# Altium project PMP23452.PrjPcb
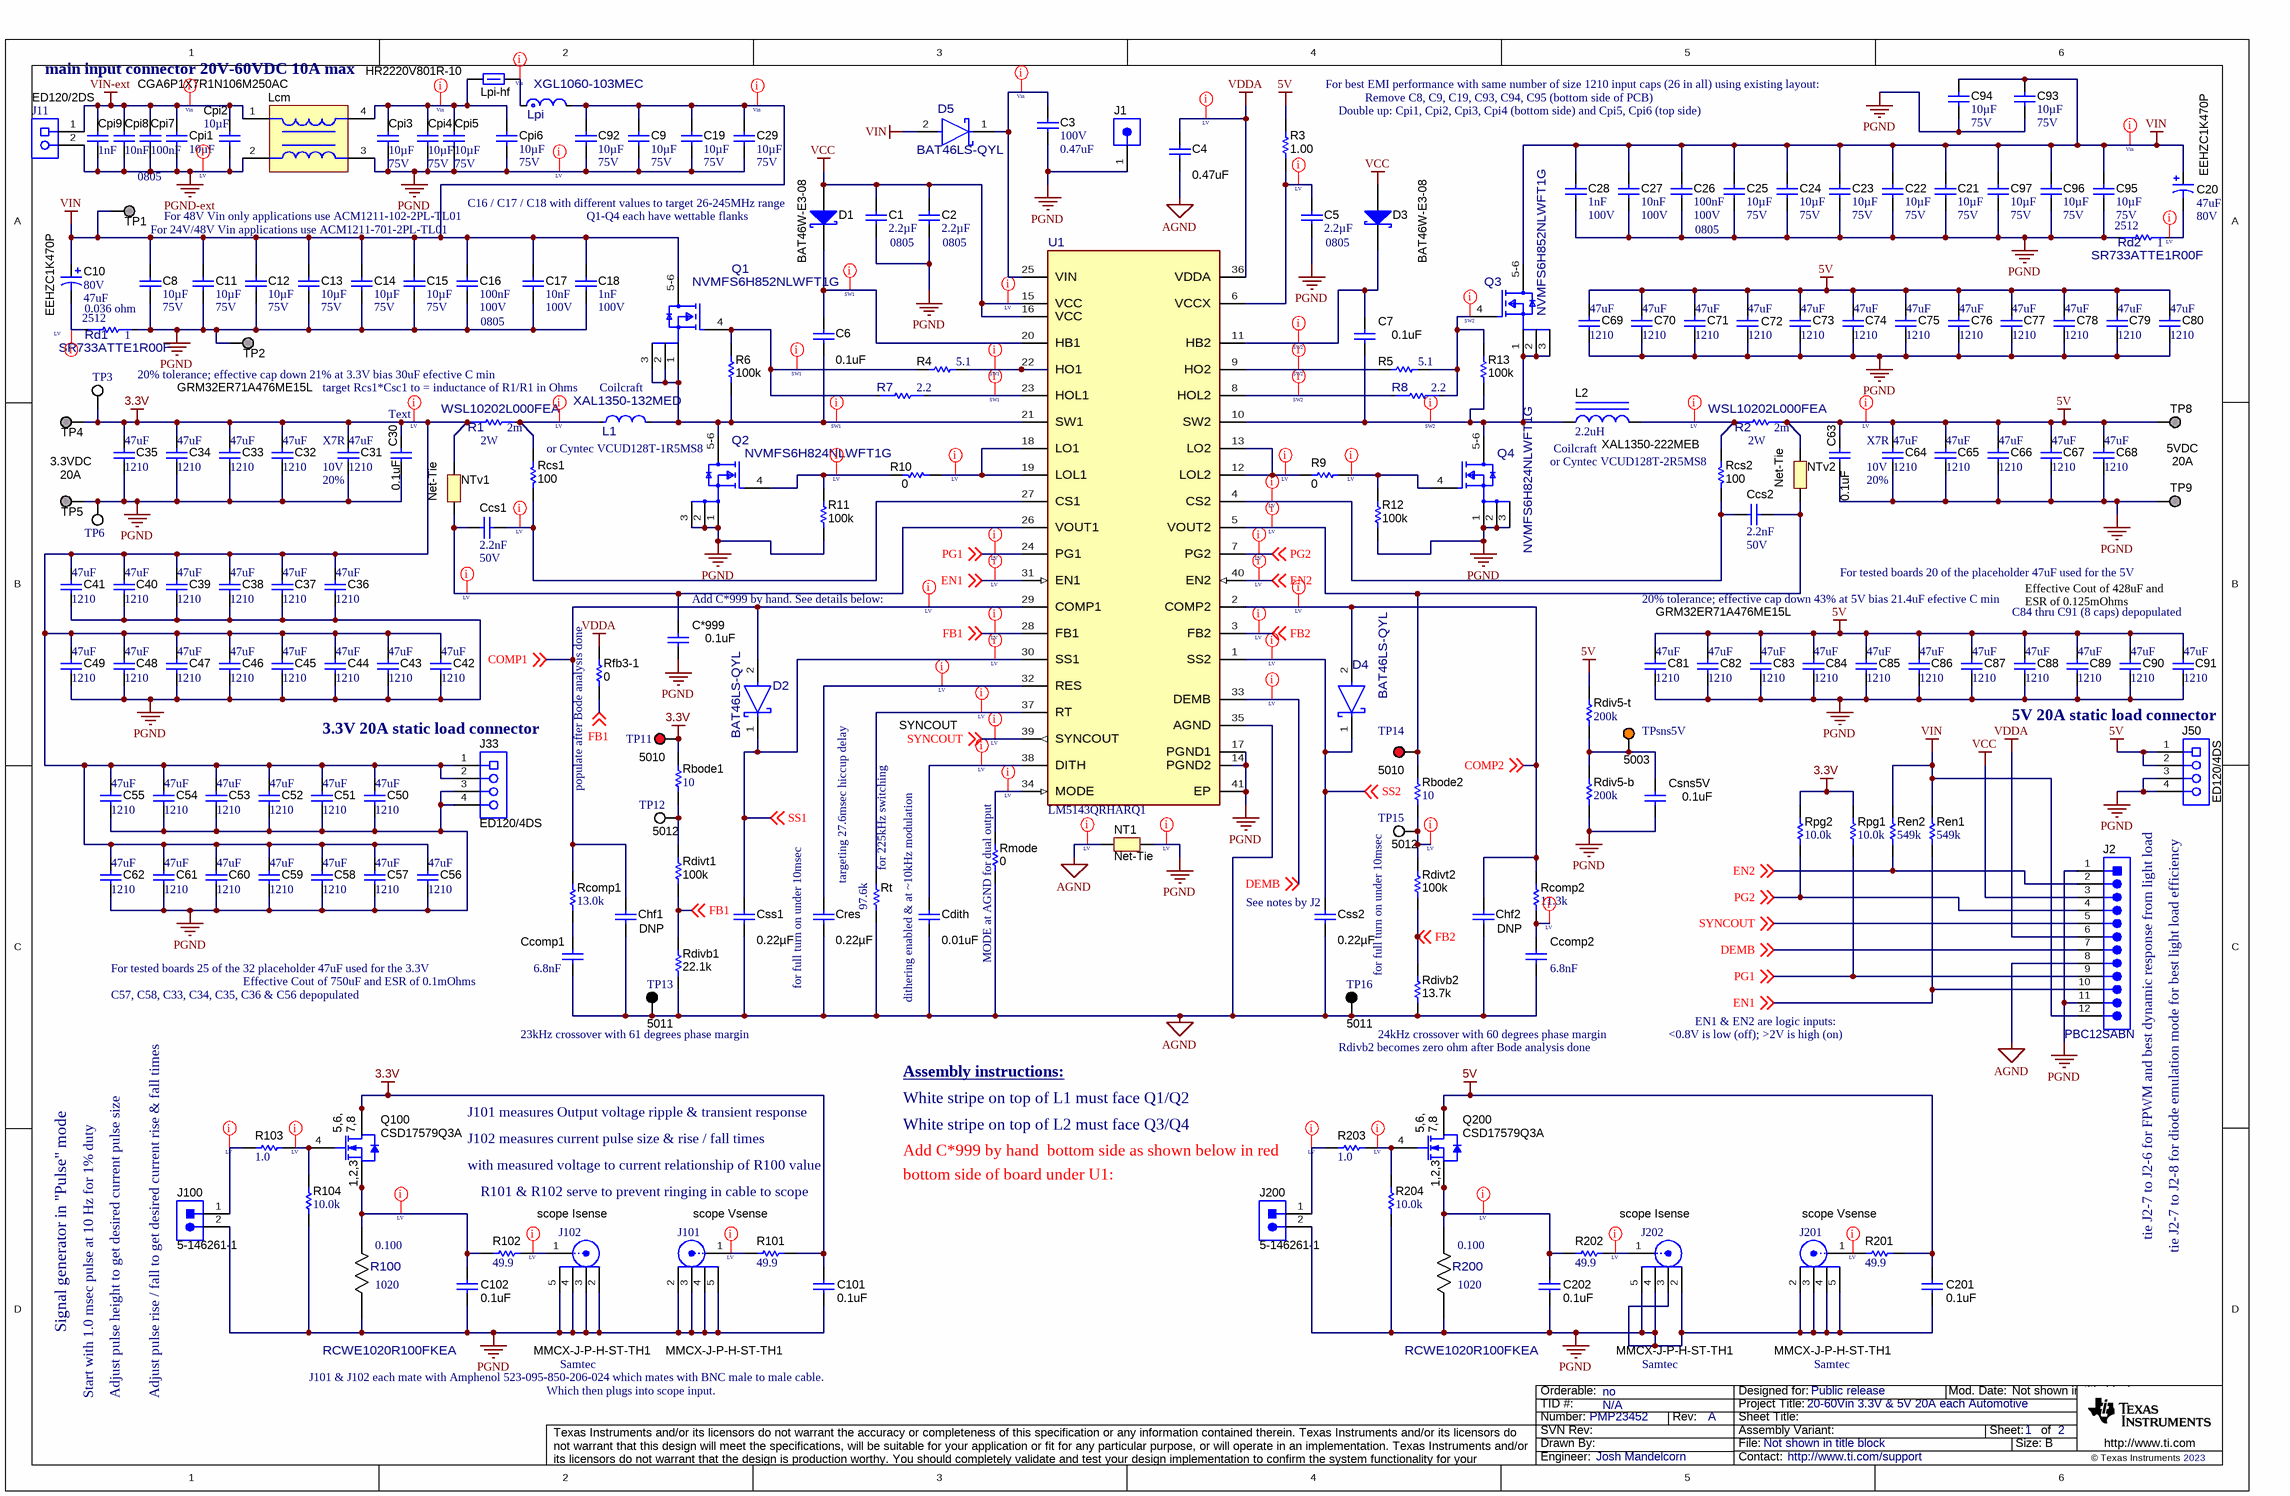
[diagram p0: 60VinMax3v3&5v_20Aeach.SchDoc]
TID: N/A; TechSupport: http://www.ti.com/support; SCH_Rev: A; PRJ_Title: 20-60Vin 3.3V & 5V 20A each Automotive; PRJ_Number: PMP23452; PRJ_Engineer: Josh Mandelcorn; PRJ_Customer: Public release; PCB_Rev: A; PCB_Layout: PMP23452; Orderable: no; EVM_Orderable: no; CopyrightYear: 2023
2 sheets, 234 parts. Net scope: global (net labels, ports and power ports of the same name join across sheets).
Board file: PMP23452.PcbDoc
Sheets:
  60VinMax3v3&5v_20Aeach.SchDoc
  PMP23452_Hardware&misc.SchDoc

## Sheet 60VinMax3v3&5v_20Aeach.SchDoc
size 431 x 279 mm; Date: Not shown in title block; ApprovedBy: Not shown in title block; CheckedBy: Not shown in title block; Author: Not shown in title block; CompanyName: Not shown in title block; Engineer: Not shown in title block; Organization: Not shown in title block; Address1: Not shown in title block; Address2: Not shown in title block; Address3: Not shown in title block; Address4: Not shown in title block; DocumentNumber: 1; Revision: Use project parameter SCH_Rev; SheetNumber: 1; SheetTotal: 2; PageSetup: Record=PageOptions¦CenterHorizontal=True¦CenterVertical=True¦PrintScale=0.96¦XCorrection=1.00¦YCorrection=1.00¦PrintKind=0¦BorderSize=5000000¦LeftOffset=0¦BottomOffset=0¦Orientation=2¦PaperLength=1000¦PaperWidth=1000¦Scale=100¦PaperSource=7¦PrintQuality=600¦MediaType=1¦DitherType=10¦PaperKind=11" x 17"¦PrintScaleMode=1

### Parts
C1  PackageReference: 0805  Cap_F: 2.2µF  [0805_HV]  (hidden comment: GCM21BR71E225KA73L)
C2  PackageReference: 0805  Cap_F: 2.2µF  [0805_HV]  (hidden comment: GCM21BR71E225KA73L)
C3  VDC_V: 100V  ValueDisplayed: 0.47uF  [1206_180M]  (hidden comment: CGA5L2X7R2A474K160AA)
C4  ValueDisplayed: 0.47uF  [0603]  (hidden comment: GCM188R71C474KA55D)
C5  PackageReference: 0805  Cap_F: 2.2µF  [0805_HV]  (hidden comment: GCM21BR71E225KA73L)
C6  ValueDisplayed: 0.1uF  [0603]  (hidden comment: CGA3E2X7R1E104K080AA)
C7  ValueDisplayed: 0.1uF  [0603]  (hidden comment: CGA3E2X7R1E104K080AA)
C8  ValueDisplayed: 10µF  VDC_V: 75V  [1210_280]  (hidden comment: CGA6P1X7R1N106M250AC)
C9  ValueDisplayed: 10µF  VDC_V: 75V  [1210_280]  (hidden comment: CGA6P1X7R1N106M250AC)
C10  EEHZC1K470P  Value1: 0.036 ohm  VDC_V: 80V  ValueDisplayed: 47uF  [SM_RADIAL_10BMM]
C11  ValueDisplayed: 10µF  VDC_V: 75V  [1210_280]  (hidden comment: CGA6P1X7R1N106M250AC)
C12  ValueDisplayed: 10µF  VDC_V: 75V  [1210_280]  (hidden comment: CGA6P1X7R1N106M250AC)
C13  ValueDisplayed: 10µF  VDC_V: 75V  [1210_280]  (hidden comment: CGA6P1X7R1N106M250AC)
C14  ValueDisplayed: 10µF  VDC_V: 75V  [1210_280]  (hidden comment: CGA6P1X7R1N106M250AC)
C15  ValueDisplayed: 10µF  VDC_V: 75V  [1210_280]  (hidden comment: CGA6P1X7R1N106M250AC)
C16  PackageReference: 0805  Cap_F: 100nF  VDC_V: 100V  [0805_HV]  (hidden comment: CGA4J2X7R2A104K125AA)
C17  Cap_F: 10nF  VDC_V: 100V  [0603]  (hidden comment: CGA3E2X7R2A103K080AA)
C18  Cap_F: 1nF  VDC_V: 100V  [0603]  (hidden comment: CGA3E2X7R2A102K080AA)
C19  ValueDisplayed: 10µF  VDC_V: 75V  [1210_280]  (hidden comment: CGA6P1X7R1N106M250AC)
C20  EEHZC1K470P  VDC_V: 80V  ValueDisplayed: 47uF  [SM_RADIAL_10BMM]
C21  ValueDisplayed: 10µF  VDC_V: 75V  [1210_280]  (hidden comment: CGA6P1X7R1N106M250AC)
C22  ValueDisplayed: 10µF  VDC_V: 75V  [1210_280]  (hidden comment: CGA6P1X7R1N106M250AC)
C23  ValueDisplayed: 10µF  VDC_V: 75V  [1210_280]  (hidden comment: CGA6P1X7R1N106M250AC)
C24  ValueDisplayed: 10µF  VDC_V: 75V  [1210_280]  (hidden comment: CGA6P1X7R1N106M250AC)
C25  ValueDisplayed: 10µF  VDC_V: 75V  [1210_280]  (hidden comment: CGA6P1X7R1N106M250AC)
C26  PackageReference: 0805  Cap_F: 100nF  VDC_V: 100V  [0805_HV]  (hidden comment: CGA4J2X7R2A104K125AA)
C27  Cap_F: 10nF  VDC_V: 100V  [0603]  (hidden comment: CGA3E2X7R2A103K080AA)
C28  Cap_F: 1nF  VDC_V: 100V  [0603]  (hidden comment: CGA3E2X7R2A102K080AA)
C29  ValueDisplayed: 10µF  VDC_V: 75V  [1210_280]  (hidden comment: CGA6P1X7R1N106M250AC)
C30  ValueDisplayed: 0.1uF  [0603L]  (hidden comment: CGA3E2X7R1E104K080AA)
C31  TempCo: X7R  Tolerance_%: 20%  Cap_Case: 1210  VDC_V: 10V  ValueDisplayed: 47uF  [1210_270]  (hidden comment: GRM32ER71A476ME15L)
C32  Cap_Case: 1210  ValueDisplayed: 47uF  [1210_270]  (hidden comment: GRM32ER71A476ME15L)
C33  Cap_Case: 1210  ValueDisplayed: 47uF  [1210_270]  (hidden comment: GRM32ER71A476ME15L)
C34  Cap_Case: 1210  ValueDisplayed: 47uF  [1210_270]  (hidden comment: GRM32ER71A476ME15L)
C35  GRM32ER71A476ME15L  Cap_Case: 1210  ValueDisplayed: 47uF  [1210_270]
C36  Cap_Case: 1210  ValueDisplayed: 47uF  [1210_270]  (hidden comment: GRM32ER71A476ME15L)
C37  Cap_Case: 1210  ValueDisplayed: 47uF  [1210_270]  (hidden comment: GRM32ER71A476ME15L)
C38  Cap_Case: 1210  ValueDisplayed: 47uF  [1210_270]  (hidden comment: GRM32ER71A476ME15L)
C39  Cap_Case: 1210  ValueDisplayed: 47uF  [1210_270]  (hidden comment: GRM32ER71A476ME15L)
C40  Cap_Case: 1210  ValueDisplayed: 47uF  [1210_270]  (hidden comment: GRM32ER71A476ME15L)
C41  Cap_Case: 1210  ValueDisplayed: 47uF  [1210_270]  (hidden comment: GRM32ER71A476ME15L)
C42  Cap_Case: 1210  ValueDisplayed: 47uF  [1210_270]  (hidden comment: GRM32ER71A476ME15L)
C43  Cap_Case: 1210  ValueDisplayed: 47uF  [1210_270]  (hidden comment: GRM32ER71A476ME15L)
C44  Cap_Case: 1210  ValueDisplayed: 47uF  [1210_270]  (hidden comment: GRM32ER71A476ME15L)
C45  Cap_Case: 1210  ValueDisplayed: 47uF  [1210_270]  (hidden comment: GRM32ER71A476ME15L)
C46  Cap_Case: 1210  ValueDisplayed: 47uF  [1210_270]  (hidden comment: GRM32ER71A476ME15L)
C47  Cap_Case: 1210  ValueDisplayed: 47uF  [1210_270]  (hidden comment: GRM32ER71A476ME15L)
C48  Cap_Case: 1210  ValueDisplayed: 47uF  [1210_270]  (hidden comment: GRM32ER71A476ME15L)
C49  Cap_Case: 1210  ValueDisplayed: 47uF  [1210_270]  (hidden comment: GRM32ER71A476ME15L)
C50  Cap_Case: 1210  ValueDisplayed: 47uF  [1210_270]  (hidden comment: GRM32ER71A476ME15L)
C51  Cap_Case: 1210  ValueDisplayed: 47uF  [1210_270]  (hidden comment: GRM32ER71A476ME15L)
C52  Cap_Case: 1210  ValueDisplayed: 47uF  [1210_270]  (hidden comment: GRM32ER71A476ME15L)
C53  Cap_Case: 1210  ValueDisplayed: 47uF  [1210_270]  (hidden comment: GRM32ER71A476ME15L)
C54  Cap_Case: 1210  ValueDisplayed: 47uF  [1210_270]  (hidden comment: GRM32ER71A476ME15L)
C55  Cap_Case: 1210  ValueDisplayed: 47uF  [1210_270]  (hidden comment: GRM32ER71A476ME15L)
C56  Cap_Case: 1210  ValueDisplayed: 47uF  [1210_270]  (hidden comment: GRM32ER71A476ME15L)
C57  Cap_Case: 1210  ValueDisplayed: 47uF  [1210_270]  (hidden comment: GRM32ER71A476ME15L)
C58  Cap_Case: 1210  ValueDisplayed: 47uF  [1210_270]  (hidden comment: GRM32ER71A476ME15L)
C59  Cap_Case: 1210  ValueDisplayed: 47uF  [1210_270]  (hidden comment: GRM32ER71A476ME15L)
C60  Cap_Case: 1210  ValueDisplayed: 47uF  [1210_270]  (hidden comment: GRM32ER71A476ME15L)
C61  Cap_Case: 1210  ValueDisplayed: 47uF  [1210_270]  (hidden comment: GRM32ER71A476ME15L)
C62  Cap_Case: 1210  ValueDisplayed: 47uF  [1210_270]  (hidden comment: GRM32ER71A476ME15L)
C63  ValueDisplayed: 0.1uF  [0603L]  (hidden comment: CGA3E2X7R1E104K080AA)
C64  TempCo: X7R  Tolerance_%: 20%  Cap_Case: 1210  VDC_V: 10V  ValueDisplayed: 47uF  [1210_270]  (hidden comment: GRM32ER71A476ME15L)
C65  Cap_Case: 1210  ValueDisplayed: 47uF  [1210_270]  (hidden comment: GRM32ER71A476ME15L)
C66  Cap_Case: 1210  ValueDisplayed: 47uF  [1210_270]  (hidden comment: GRM32ER71A476ME15L)
C67  Cap_Case: 1210  ValueDisplayed: 47uF  [1210_270]  (hidden comment: GRM32ER71A476ME15L)
C68  Cap_Case: 1210  ValueDisplayed: 47uF  [1210_270]  (hidden comment: GRM32ER71A476ME15L)
C69  Cap_Case: 1210  ValueDisplayed: 47uF  [1210_270]  (hidden comment: GRM32ER71A476ME15L)
C70  Cap_Case: 1210  ValueDisplayed: 47uF  [1210_270]  (hidden comment: GRM32ER71A476ME15L)
C71  Cap_Case: 1210  ValueDisplayed: 47uF  [1210_270]  (hidden comment: GRM32ER71A476ME15L)
C72  Cap_Case: 1210  ValueDisplayed: 47uF  [1210_270]  (hidden comment: GRM32ER71A476ME15L)
C73  Cap_Case: 1210  ValueDisplayed: 47uF  [1210_270]  (hidden comment: GRM32ER71A476ME15L)
C74  Cap_Case: 1210  ValueDisplayed: 47uF  [1210_270]  (hidden comment: GRM32ER71A476ME15L)
C75  Cap_Case: 1210  ValueDisplayed: 47uF  [1210_270]  (hidden comment: GRM32ER71A476ME15L)
C76  Cap_Case: 1210  ValueDisplayed: 47uF  [1210_270]  (hidden comment: GRM32ER71A476ME15L)
C77  Cap_Case: 1210  ValueDisplayed: 47uF  [1210_270]  (hidden comment: GRM32ER71A476ME15L)
C78  Cap_Case: 1210  ValueDisplayed: 47uF  [1210_270]  (hidden comment: GRM32ER71A476ME15L)
C79  Cap_Case: 1210  ValueDisplayed: 47uF  [1210_270]  (hidden comment: GRM32ER71A476ME15L)
C80  Cap_Case: 1210  ValueDisplayed: 47uF  [1210_270]  (hidden comment: GRM32ER71A476ME15L)
C81  GRM32ER71A476ME15L  Cap_Case: 1210  ValueDisplayed: 47uF  [1210_270]
C82  Cap_Case: 1210  ValueDisplayed: 47uF  [1210_270]  (hidden comment: GRM32ER71A476ME15L)
C83  Cap_Case: 1210  ValueDisplayed: 47uF  [1210_270]  (hidden comment: GRM32ER71A476ME15L)
C84  Cap_Case: 1210  ValueDisplayed: 47uF  [1210_270]  (hidden comment: GRM32ER71A476ME15L)
C85  Cap_Case: 1210  ValueDisplayed: 47uF  [1210_270]  (hidden comment: GRM32ER71A476ME15L)
C86  Cap_Case: 1210  ValueDisplayed: 47uF  [1210_270]  (hidden comment: GRM32ER71A476ME15L)
C87  Cap_Case: 1210  ValueDisplayed: 47uF  [1210_270]  (hidden comment: GRM32ER71A476ME15L)
C88  Cap_Case: 1210  ValueDisplayed: 47uF  [1210_270]  (hidden comment: GRM32ER71A476ME15L)
C89  Cap_Case: 1210  ValueDisplayed: 47uF  [1210_270]  (hidden comment: GRM32ER71A476ME15L)
C90  Cap_Case: 1210  ValueDisplayed: 47uF  [1210_270]  (hidden comment: GRM32ER71A476ME15L)
C91  Cap_Case: 1210  ValueDisplayed: 47uF  [1210_270]  (hidden comment: GRM32ER71A476ME15L)
C92  ValueDisplayed: 10µF  VDC_V: 75V  [1210_280]  (hidden comment: CGA6P1X7R1N106M250AC)
C93  ValueDisplayed: 10µF  VDC_V: 75V  [1210_280]  (hidden comment: CGA6P1X7R1N106M250AC)
C94  ValueDisplayed: 10µF  VDC_V: 75V  [1210_280]  (hidden comment: CGA6P1X7R1N106M250AC)
C95  ValueDisplayed: 10µF  VDC_V: 75V  [1210_280]  (hidden comment: CGA6P1X7R1N106M250AC)
C96  ValueDisplayed: 10µF  VDC_V: 75V  [1210_280]  (hidden comment: CGA6P1X7R1N106M250AC)
C97  ValueDisplayed: 10µF  VDC_V: 75V  [1210_280]  (hidden comment: CGA6P1X7R1N106M250AC)
C101  ValueDisplayed: 0.1uF  [0603]  (hidden comment: CGA3E2X7R1E104K080AA)
C102  ValueDisplayed: 0.1uF  [0603]  (hidden comment: CGA3E2X7R1E104K080AA)
C201  ValueDisplayed: 0.1uF  [0603]  (hidden comment: CGA3E2X7R1E104K080AA)
C202  ValueDisplayed: 0.1uF  [0603]  (hidden comment: CGA3E2X7R1E104K080AA)
C*999  ValueDisplayed: 0.1uF  [0603]  (hidden comment: CGA3E2X7R1E104K080AA)
Ccomp1  Cap_F: 6.8nF  [0603]  (hidden comment: CGA3E2X7R2A682K080AA)
Ccomp2  Cap_F: 6.8nF  [0603]  (hidden comment: CGA3E2X7R2A682K080AA)
Ccs1  Cap_F: 2.2nF  VDC_V: 50V  [0603]  (hidden comment: C0603C222K5RAC)
Ccs2  Cap_F: 2.2nF  VDC_V: 50V  [0603]  (hidden comment: C0603C222K5RAC)
Cdith  ValueDisplayed: 0.01uF  [0603]  (hidden comment: GRM188R72A103KA01D)
Chf1  DNP  [0603]
Chf2  DNP  [0603]
Cpi1  CGA6P1X7R1N106M250AC  ValueDisplayed: 10µF  [1210_280]
Cpi2  ValueDisplayed: 10µF  [1210_280]  (hidden comment: CGA6P1X7R1N106M250AC)
Cpi3  ValueDisplayed: 10µF  VDC_V: 75V  [1210_280]  (hidden comment: CGA6P1X7R1N106M250AC)
Cpi4  ValueDisplayed: 10µF  VDC_V: 75V  [1210_280]  (hidden comment: CGA6P1X7R1N106M250AC)
Cpi5  ValueDisplayed: 10µF  VDC_V: 75V  [1210_280]  (hidden comment: CGA6P1X7R1N106M250AC)
Cpi6  ValueDisplayed: 10µF  VDC_V: 75V  [1210_280]  (hidden comment: CGA6P1X7R1N106M250AC)
Cpi7  PackageReference: 0805  Cap_F: 100nF  [0805_HV]  (hidden comment: CGA4J2X7R2A104K125AA)
Cpi8  Cap_F: 10nF  [0603]  (hidden comment: CGA3E2X7R2A103K080AA)
Cpi9  Cap_F: 1nF  [0603]  (hidden comment: CGA3E2X7R2A102K080AA)
Cres  ValueDisplayed: 0.22µF  [0603]  (hidden comment: CL10B224KO8VPNC)
Csns5V  ValueDisplayed: 0.1uF  [0603]  (hidden comment: CGA3E2X7R1E104K080AA)
Css1  ValueDisplayed: 0.22µF  [0603]  (hidden comment: CL10B224KO8VPNC)
Css2  ValueDisplayed: 0.22µF  [0603]  (hidden comment: CL10B224KO8VPNC)
D1  BAT46W-E3-08  [SOD-123]
D2  BAT46LS-QYL  [FP-BAT46LS-QYL_DFN1006BD-2-0]
D3  BAT46W-E3-08  [SOD-123]
D4  BAT46LS-QYL  [FP-BAT46LS-QYL_DFN1006BD-2-0]
D5  BAT46LS-QYL  [FP-BAT46LS-QYL_DFN1006BD-2-0]
J1  1040  [CONN_1040]  (value not drawn)
J2  PBC12SABN  [Sullins_PxC12SABN]
J11  ED120/2DS  [On-Shore_ED120_2DS]
J33  ED120/4DS  [On-Shore_ED120_4DS]
J50  ED120/4DS  [On-Shore_ED120_4DS]
J100  5-146261-1  [CONN_5-146261-1]
J101  MMCX-J-P-H-ST-TH1  [Samtec_MMCX-J-P-H-ST-TH1]
J102  MMCX-J-P-H-ST-TH1  Manufacturer: Samtec  [Samtec_MMCX-J-P-H-ST-TH1]
J200  5-146261-1  [CONN_5-146261-1]
J201  MMCX-J-P-H-ST-TH1  Manufacturer: Samtec  [Samtec_MMCX-J-P-H-ST-TH1]
J202  MMCX-J-P-H-ST-TH1  Manufacturer: Samtec  [Samtec_MMCX-J-P-H-ST-TH1]
L1  XAL1350-132MED  Manufacturer: Coilcraft  [FP-XAL1350-132MED_SMT_INDUCTOR_13MM0_14MM0-MFG]
L2  XAL1350-222MEB  Manufacturer: Coilcraft  ValueDisplayed: 2.2uH  [XAL1350]
Lcm  ACM1211-701-2PL-TL01  [TDK_ACM1211]  (value not drawn)
Lpi  XGL1060-103MEC  [FP-XGL1060-103MEC_SMT2_10MM0_11MM3-MFG]
Lpi-hf  HR2220V801R-10  [2220_390]
NT1  Net-Tie  [Net-Tie_10mil]  (net tie, no BOM)
NTv1  Net-Tie  [Net-Tie_10mil]  (net tie, no BOM)
NTv2  Net-Tie  [Net-Tie_10mil]  (net tie, no BOM)
Q1  NVMFS6H852NLWFT1G  [FP-NVMFS6H852NLWFT1G_DFN5-MFG]
Q2  NVMFS6H824NLWFT1G  [FP-NVMFS6H824NLWFT1G_DFNW5-5x6-MFG]
Q3  NVMFS6H852NLWFT1G  [FP-NVMFS6H852NLWFT1G_DFN5-MFG]
Q4  NVMFS6H824NLWFT1G  [FP-NVMFS6H824NLWFT1G_DFNW5-5x6-MFG]
Q100  CSD17579Q3A  [DNH0008A]
Q200  CSD17579Q3A  [DNH0008A]
R1  WSL10202L000FEA  value 2m  Power_W: 2W  [FP-WSL10202L000FEA_1020-MFG]
R2  WSL10202L000FEA  value 2m  Power_W: 2W  [FP-WSL10202L000FEA_1020-MFG]
R3  ValueDisplayed: 1.00  [0603]  (hidden comment: RC0603FR-071RL)
R4  ValueDisplayed: 5.1  [0603]  (hidden comment: CRCW06035R10JNEA)
R5  ValueDisplayed: 5.1  [0603]  (hidden comment: CRCW06035R10JNEA)
R6  ValueDisplayed: 100k  [0603]  (hidden comment: CRCW0603100KFKEA)
R7  value 2.2  [FP-CRCW06032R20JNEA_0603-MFG]  (hidden comment: CRCW06032R20JNEA)
R8  value 2.2  [FP-CRCW06032R20JNEA_0603-MFG]  (hidden comment: CRCW06032R20JNEA)
R9  ValueDisplayed: 0  [0603]  (hidden comment: CRCW06030000Z0EA)
R10  ValueDisplayed: 0  [0603]  (hidden comment: CRCW06030000Z0EA)
R11  ValueDisplayed: 100k  [0603]  (hidden comment: CRCW0603100KFKEA)
R12  ValueDisplayed: 100k  [0603]  (hidden comment: CRCW0603100KFKEA)
R13  ValueDisplayed: 100k  [0603]  (hidden comment: CRCW0603100KFKEA)
R100  RCWE1020R100FKEA  Res_ohm: 0.100  PackageReference: 1020  [FP-RCWE1020R115FKEA_1020-MFG]
R101  ValueDisplayed: 49.9  [0603]  (hidden comment: CRCW060349R9FKEA)
R102  ValueDisplayed: 49.9  [0603]  (hidden comment: CRCW060349R9FKEA)
R103  ValueDisplayed: 1.0  [0603]  (hidden comment: CRCW06031R00JNEA)
R104  ValueDisplayed: 10.0k  [0603]  (hidden comment: CRCW060310K0FKEA)
R200  RCWE1020R100FKEA  Res_ohm: 0.100  PackageReference: 1020  [FP-RCWE1020R115FKEA_1020-MFG]
R201  ValueDisplayed: 49.9  [0603]  (hidden comment: CRCW060349R9FKEA)
R202  ValueDisplayed: 49.9  [0603]  (hidden comment: CRCW060349R9FKEA)
R203  ValueDisplayed: 1.0  [0603]  (hidden comment: CRCW06031R00JNEA)
R204  ValueDisplayed: 10.0k  [0603]  (hidden comment: CRCW060310K0FKEA)
Rbode1  ValueDisplayed: 10  [0603]  (hidden comment: CRCW060310R0JNEAHP)
Rbode2  ValueDisplayed: 10  [0603]  (hidden comment: CRCW060310R0JNEAHP)
Rcomp1  ValueDisplayed: 13.0k  [0603]  (hidden comment: CRCW060313K0FKEA)
Rcomp2  ValueDisplayed: 11.3k  [0603]  (hidden comment: CRCW060311K3FKEA)
Rcs1  ValueDisplayed: 100  [0603]  (hidden comment: CRCW0603100RFKEA)
Rcs2  ValueDisplayed: 100  [0603]  (hidden comment: CRCW0603100RFKEA)
Rd1  SR733ATTE1R00F  PackageReference: 2512  Res_ohm: 1  [FP-SR733ATTE1R00F_2512-MFG]
Rd2  SR733ATTE1R00F  PackageReference: 2512  Res_ohm: 1  [FP-SR733ATTE1R00F_2512-MFG]
Rdiv5-b  ValueDisplayed: 200k  [0603]  (hidden comment: CRCW0603200KFKEA)
Rdiv5-t  ValueDisplayed: 200k  [0603]  (hidden comment: CRCW0603200KFKEA)
Rdivb1  ValueDisplayed: 22.1k  [0603]  (hidden comment: CRCW060322K1FKEA)
Rdivb2  ValueDisplayed: 13.7k  [0603]  (hidden comment: CRCW060313K7FKEA)
Rdivt1  ValueDisplayed: 100k  [0603]  (hidden comment: CRCW0603100KFKEA)
Rdivt2  ValueDisplayed: 100k  [0603]  (hidden comment: CRCW0603100KFKEA)
Ren1  ValueDisplayed: 549k  [0603]  (hidden comment: CRCW0603549KFKEA)
Ren2  ValueDisplayed: 549k  [0603]  (hidden comment: CRCW0603549KFKEA)
Rfb3-1  ValueDisplayed: 0  [0603]  (hidden comment: CRCW06030000Z0EA)
Rmode  ValueDisplayed: 0  [0603]  (hidden comment: CRCW06030000Z0EA)
Rpg1  ValueDisplayed: 10.0k  [0603]  (hidden comment: CRCW060310K0FKEA)
Rpg2  ValueDisplayed: 10.0k  [0603]  (hidden comment: CRCW060310K0FKEA)
Rt  ValueDisplayed: 97.6k  [0603]  (hidden comment: CRCW060397K6FKEA)
TP1  1598-2  [Keystone1598-2]  (value not drawn)
TP2  1598-2  [Keystone1598-2]  (value not drawn)
TP3  5015  [Testpoint_Keystone_Miniature]  (value not drawn)
TP4  1598-2  [Keystone1598-2]  (value not drawn)
TP5  1598-2  [Keystone1598-2]  (value not drawn)
TP6  5015  [Testpoint_Keystone_Miniature]  (value not drawn)
TP8  1598-2  [Keystone1598-2]  (value not drawn)
TP9  1598-2  [Keystone1598-2]  (value not drawn)
TP11  5010  [Keystone5010]
TP12  5012  [Keystone5012]
TP13  5011  [Keystone5011]
TP14  5010  [Keystone5010]
TP15  5012  [Keystone5012]
TP16  5011  [Keystone5011]
TPsns5V  5003  [Keystone5003]
U1  LM5143QRHARQ1  [RHA0040N-MFG]

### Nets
3.3V: C30.1 C31.1 C32.1 C33.1 C34.1 C35.1 C36.1 C37.1 C38.1 C39.1 C40.1 C41.1 C42.1 C43.1 C44.1 C45.1 C46.1 C47.1 C48.1 C49.1 C50.1 C51.1 C52.1 C53.1 C54.1 C55.1 C56.1 C57.1 C58.1 C59.1 C60.1 C61.1 C62.1 C101.2 J33.1 J33.2 NTv1.2 Q100.5(D) Q100.6(D) Q100.7(D) Q100.8(D) Q100.9(D) R1.1 R101.2 Rbode1.2 Rpg1.2 Rpg2.2 TP3.1 TP4.1 TP11.1
5V: C63.1 C64.1 C65.1 C66.1 C67.1 C68.1 C69.1 C70.1 C71.1 C72.1 C73.1 C74.1 C75.1 C76.1 C77.1 C78.1 C79.1 C80.1 C81.1 C82.1 C83.1 C84.1 C85.1 C86.1 C87.1 C88.1 C89.1 C90.1 C91.1 C201.2 J50.1 J50.2 NTv2.2 Q200.5(D) Q200.6(D) Q200.7(D) Q200.8(D) Q200.9(D) R2.2 R3.2 R201.2 Rdiv5-t.2 TP8.1
AGND: C4.1 Ccomp1.2 Ccomp2.2 Cdith.2 Chf1.2 Chf2.2 Cres.2 Css1.2 Css2.2 J2.8 NT1.1 Rdivb1.1 Rdivb2.1 Rmode.1 Rt.1 TP13.1 TP16.1 U1.35(AGND)
PGND: C1.2 C2.2 C3.2 C5.2 C8.2 C9.2 C11.2 C12.2 C13.2 C14.2 C15.2 C16.2 C17.2 C18.2 C19.2 C21.2 C22.2 C23.2 C24.2 C25.2 C26.2 C27.2 C28.2 C29.2 C30.2 C31.2 C32.2 C33.2 C34.2 C35.2 C36.2 C37.2 C38.2 C39.2 C40.2 C41.2 C42.2 C43.2 C44.2 C45.2 C46.2 C47.2 C48.2 C49.2 C50.2 C51.2 C52.2 C53.2 C54.2 C55.2 C56.2 C57.2 C58.2 C59.2 C60.2 C61.2 C62.2 C63.2 C64.2 C65.2 C66.2 C67.2 C68.2 C69.2 C70.2 C71.2 C72.2 C73.2 C74.2 C75.2 C76.2 C77.2 C78.2 C79.2 C80.2 C81.2 C82.2 C83.2 C84.2 C85.2 C86.2 C87.2 C88.2 C89.2 C90.2 C91.2 C92.2 C93.2 C94.2 C95.2 C96.2 C97.2 C101.1 C102.1 C201.1 C202.1 C*999.1 Cpi3.2 Cpi4.2 Cpi5.2 Cpi6.2 Csns5V.1 J1.1 J2.1 J2.11 J33.3 J33.4 J50.3 J50.4 J100.2 J101.2 J101.3 J101.4 J101.5 J102.2 J102.3 J102.4 J102.5 J200.2 J201.2 J201.3 J201.4 J201.5 J202.2 J202.3 J202.4 J202.5 Lcm.3 NT1.2 Q2.1(S) Q2.2(S) Q2.3(S) Q4.1(S) Q4.2(S) Q4.3(S) R11.1 R12.1 R100.1 R104.1 R200.1 R204.1 Rd1.2 Rd2.1 Rdiv5-b.1 TP2.1 TP5.1 TP6.1 TP9.1 U1.14(PGND2) U1.17(PGND1) U1.41(EP)
PGND-ext: Cpi1.2 Cpi2.2 Cpi7.2 Cpi8.2 Cpi9.2 J11.2 Lcm.2
VCC: C1.1 C2.1 D1.2(A) D3.2(A) J2.3 U1.15(VCC) U1.16(VCC)
VDDA: C4.2 J2.6 Rfb3-1.2 U1.36(VDDA)
VIN: C8.1 C9.1 C10.1(+) C11.1 C12.1 C13.1 C14.1 C15.1 C16.1 C17.1 C18.1 C19.1 C20.1(+) C21.1 C22.1 C23.1 C24.1 C25.1 C26.1 C27.1 C28.1 C29.1 C92.1 C93.1 C94.1 C95.1 C96.1 C97.1 D5.2(A) J2.12 Lpi.2 Q1.5-6(D) Q3.5-6(D) Ren1.2 Ren2.2 TP1.1
VIN-ext: Cpi1.1 Cpi2.1 Cpi7.1 Cpi8.1 Cpi9.1 J11.1 Lcm.1
COMP1: Chf1.1 D2.2(A) Rcomp1.2 U1.29(COMP1) ; off-sheet COMP1
COMP2: Chf2.1 D4.2(A) Rcomp2.2 U1.2(COMP2) ; off-sheet COMP2
DEMB: J2.7 U1.33(DEMB) ; off-sheet DEMB
EN1: J2.10 Ren1.1 U1.31(EN1) ; off-sheet EN1
EN2: J2.2 Ren2.1 U1.40(EN2) ; off-sheet EN2
FB1: Rdivb1.2 Rdivt1.1 Rfb3-1.1 U1.28(FB1) ; off-sheet FB1
FB2: Rdivb2.2 Rdivt2.1 U1.3(FB2) ; off-sheet FB2
PG1: J2.9 Rpg1.1 U1.24(PG1) ; off-sheet PG1
PG2: J2.4 Rpg2.1 U1.7(PG2) ; off-sheet PG2
SS1: Css1.1 D2.1(K) U1.30(SS1) ; off-sheet SS1
SS2: Css2.1 D4.1(K) U1.1(SS2) ; off-sheet SS2
SYNCOUT: J2.5 U1.39(SYNCOUT) ; off-sheet SYNCOUT
NetC3_1: C3.1 D5.1(K) U1.25(VIN)
NetC5_1: C5.1 R3.1 U1.6(VCCX)
NetC6_1: C6.1 L1.2 Q1.1(S) Q1.2(S) Q1.3(S) Q2.5-6(D) R6.1 U1.21(SW1)
NetC6_2: C6.2 D1.1(K) U1.20(HB1)
NetC7_1: C7.1 L2.1 Q3.1(S) Q3.2(S) Q3.3(S) Q4.5-6(D) R13.1 U1.10(SW2)
NetC7_2: C7.2 D3.1(K) U1.11(HB2)
NetC10_2: C10.2(-) Rd1.1
NetC20_2: C20.2(-) Rd2.2
NetC102_2: C102.2 Q100.1(S) Q100.2(S) Q100.3(S) R100.2 R102.1
NetC202_2: C202.2 Q200.1(S) Q200.2(S) Q200.3(S) R200.2 R202.1
NetC*999_2: C*999.2 Ccs1.2 NTv1.1 U1.26(VOUT1)
NetCcomp1_1: Ccomp1.1 Rcomp1.1
NetCcomp2_1: Ccomp2.1 Rcomp2.1
NetCcs1_1: Ccs1.1 Rcs1.1 U1.27(CS1)
NetCcs2_1: Ccs2.1 NTv2.1 Rbode2.2 TP14.1 U1.5(VOUT2)
NetCcs2_2: Ccs2.2 Rcs2.1 U1.4(CS2)
NetCdith_1: Cdith.1 U1.38(DITH)
NetCpi3_1: Cpi3.1 Cpi4.1 Cpi5.1 Cpi6.1 Lcm.4 Lpi-hf.1
NetCres_1: Cres.1 U1.32(RES)
NetCsns5V_2: Csns5V.2 Rdiv5-b.2 Rdiv5-t.1 TPsns5V.1
NetJ100_1: J100.1 R103.1
NetJ101_1: J101.1 R101.1
NetJ102_1: J102.1 R102.2
NetJ200_1: J200.1 R203.1
NetJ201_1: J201.1 R201.1
NetJ202_1: J202.1 R202.2
NetL1_1: L1.1 R1.2 Rcs1.2
NetL2_2: L2.2 R2.1 Rcs2.2
NetLpi_1: Lpi.1 Lpi-hf.2
NetQ1_4: Q1.4(G) R4.1 R6.2 R7.1
NetQ2_4: Q2.4(G) R10.2 R11.2
NetQ3_4: Q3.4(G) R5.2 R8.2 R13.2
NetQ4_4: Q4.4(G) R9.2 R12.2
NetQ100_4: Q100.4(G) R103.2 R104.2
NetQ200_4: Q200.4(G) R203.2 R204.2
NetR4_2: R4.2 U1.22(HO1)
NetR5_1: R5.1 U1.9(HO2)
NetR7_2: R7.2 U1.23(HOL1)
NetR8_1: R8.1 U1.8(HOL2)
NetR9_1: R9.1 U1.12(LOL2) U1.13(LO2)
NetR10_1: R10.1 U1.18(LO1) U1.19(LOL1)
NetRbode1_1: Rbode1.1 Rdivt1.2 TP12.1
NetRbode2_1: Rbode2.1 Rdivt2.2 TP15.1
NetRmode_2: Rmode.2 U1.34(MODE)
NetRt_2: Rt.2 U1.37(RT)

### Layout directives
net class SW1: NetC6_1, NetC6_2, NetQ1_4, NetR4_2, NetR7_2
net class Vin: NetC3_1, NetCpi3_1, NetLpi_1, VIN, VIN-ext
net class LV: 3.3V, 5V, AGND, COMP1, COMP2, DEMB, EN1, EN2, FB1, FB2, NetC5_1, NetC10_2, NetC20_2, NetC102_2, NetC202_2, NetC*999_2, NetCcomp2_1, NetCcs1_1, NetCcs2_1, NetCcs2_2, NetCdith_1, NetCres_1, NetJ100_1, NetJ101_1, NetJ102_1, NetJ200_1, NetJ201_1, NetJ202_1, NetL1_1, NetL2_2, NetQ2_4, NetQ4_4, NetQ100_4, NetQ200_4, NetR9_1, NetR10_1, NetRbode2_1, NetRmode_2, NetRt_2, PG1, PG2, PGND, PGND-ext, SS1, SS2, SYNCOUT, VCC, VDDA
net class SW2: NetC7_1, NetC7_2, NetQ3_4, NetR5_1, NetR8_1

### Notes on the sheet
- main input connector 20V-60VDC 10A max
- For best EMI performance with same number of size 1210 input caps (26 in all) using existing layout:
- Double up: Cpi1, Cpi2, Cpi3, Cpi4 (bottom side) and Cpi5, Cpi6 (top side)
- Remove C8, C9, C19, C93, C94, C95 (bottom side of PCB)
- For 24V/48V Vin applications use ACM1211-701-2PL-TL01
- For 48V Vin only applications use ACM1211-102-2PL-TL01
- (near D1) C16 / C17 / C18 with different values to target 26-245MHz range
- Q1-Q4 each have wettable flanks
- 20% tolerance; effective cap down 21% at 3.3V bias 30uF efective C min
- target Rcs1*Csc1 to = inductance of R1/R1 in Ohms
- 3.3VDC
- (near C30) Text
- (near Q2) or Cyntec VCUD128T-1R5MS8
- or Cyntec VCUD128T-2R5MS8
- (near TP8) 5VDC
- 20A
- (near TP5) 20A
- For tested boards 20 of the placeholder 47uF used for the 5V
- (near C*999) Add C*999 by hand. See details below:
- 20% tolerance; effective cap down 43% at 5V bias 21.4uF efective C min
- C84 thru C91 (8 caps) depopulated
- Effective Cout of 428uF and ESR of 0.125mOhms
- SYNCOUT
- 5V 20A static load connector
- (near J33) 3.3V 20A static load connector
- (near Rfb3-1) populate after Bode analysis done
- targeting 27.6msec hiccup delay
- (near Rt) for 225kHz switching
- (near Css2) See notes by J2
- For tested boards 25 of the 32 placeholder 47uF used for the 3.3V
- Effective Cout of 750uF and ESR of 0.1mOhms
- (near Cres) for full turn on under 10msec
- (near Rmode) MODE at AGND for dual output
- for full turn on under 10msec
- C57, C58, C33, C34, C35, C36 & C56 depopulated
- (near TP13) 23kHz crossover with 61 degrees phase margin
- (near Cdith) dithering enabled & at
  0kHz modulation
- Rdivb2 becomes zero ohm after Bode analysis done
- 24kHz crossover with 60 degrees phase margin
- <0.8V is low (off); >2V is high (on)
- EN1 & EN2 are logic inputs:
- J101 measures Output voltage ripple & transient response
- White stripe on top of L1 must face Q1/Q2
- Assembly instructions:
- J102 measures current pulse size & rise / fall times
- with measured voltage to current relationship of R100 value
- (near R203) Add C*999 by hand  bottom side as shown below in red
- White stripe on top of L2 must face Q3/Q4
- bottom side of board under U1:
- R101 & R102 serve to prevent ringing in cable to scope
- scope Isense
- scope Vsense
- tie J2-7 to J2-6 for FPWM and best dynamic response from light load
- (near J50) tie J2-7 to J2-8 for diode emulation mode for best light load efficiency
- Signal generator in "Pulse" mode
- J101 & J102 each mate with Amphenol 523-095-850-206-024 which mates with BNC male to male cable.
- Start with 1.0 msec pulse at 10 Hz for 1% duty
- Adjust pulse height to get desired current pulse size
- Adjust pulse rise / fall to get desired current rise & fall times
- Which then plugs into scope input.

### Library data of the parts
C1 C2 C5 = CMP-0083622-1: CAP, CERM, 2.2 µF, 25 V,+/- 10%, X7R, AEC-Q200 Grade 1, 0805; Manufacturer: MuRata; TaMin_C: -55°C; Polarized: N; SizeAreaWB_mm2: 6.75; U/M: EA; Value: 2.2uF; TaMax_C: 125°C; SizeZ_mm: 1.45; SizeX_mm: 2; SizeY_mm: 1.25; Value2: 25V; SizeArea_mm2: 2.5; AEC Qualified: Y; AEC Grade: 1; AEC Category: Q200
C3 = CMP-0008781-2: CAP, CERM, 0.47 uF, 100 V, +/- 10%, X7R, AEC-Q200 Grade 1, 1206; Manufacturer: TDK; TaMin_C: -55°C; ESR_ohm: 7.558m; Polarized: N; SizeAreaWB_mm2: 10.92; Value1: 0.007558 ohm; U/M: EA; Value: 0.47uF; TaMax_C: 125°C; SizeZ_mm: 1.8; SizeX_mm: 3.2; SizeY_mm: 1.6; Cap_Case: 1206_180; SizeArea_mm2: 5.12; AEC Qualified: Y; Cap_F: 470nF; IRMS_A: 2.6472A; AEC Grade: 1; AEC Category: Q200
C4 = CMP-0007138-4: CAP, CERM, 0.47 uF, 16 V, +/- 10%, X7R, AEC-Q200 Grade 1, 0603; Manufacturer: MuRata; TaMin_C: -55°C; Polarized: N; SizeAreaWB_mm2: 4.68; Value1: Unknown; U/M: EA; Value: 0.47uF; TaMax_C: 125°C; SizeZ_mm: 1; SizeX_mm: 1.6; SizeY_mm: 0.8; Value2: 16V; SizeArea_mm2: 1.28; CompType: Capacitor; AEC Qualified: Y; Cap_F: 470nF; AEC Category: Q200
C6 C7 C101 C102 C201 C202 C*999 Csns5V = CMP-0007077-5: CAP, CERM, 0.1 uF, 25 V, +/- 10%, X7R, AEC-Q200 Grade 1, 0603; Manufacturer: TDK; TaMin_C: -55°C; Polarized: N; SizeAreaWB_mm2: 4.68; Value1: Unknown; U/M: EA; Value: 0.1uF; TaMax_C: 125°C; SizeZ_mm: 1; SizeX_mm: 1.6; SizeY_mm: 0.8; Value2: 25V; SizeArea_mm2: 1.28; AEC Qualified: Y; Cap_F: 100nF; AEC Category: Q200
C8 C9 C11-C15 C19 C21-C25 C29 C92-C97 Cpi3-Cpi6 = CMP-0085951-1: CAP, CERM, 10 µF, 75 V,+/- 20%, X7R, AEC-Q200 Grade 1, 1210; Manufacturer: TDK; SizeX_mm: 3.2; Cap_Case: 1210; AEC Qualified: Y; Polarized: N; AEC Category: Q200; U/M: EA; SizeZ_mm: 2.8; SizeY_mm: 2.5; TaMin_C: -55°C; AEC Grade: 1; SizeAreaWB_mm2: 14.7; SizeArea_mm2: 8; TaMax_C: 125°C; Value: 10uF
C10 = CMP-0012603-3: CAP, Polymer Hybrid, 47 uF, 80 V, +/- 20%, 36 mohm, 10x10 SMD; Manufacturer: Panasonic; TaMin_C: -55°C; ESR_ohm: 30; Polarized: Y; SizeAreaWB_mm2: 159.9; Value: 56uF; TaMax_C: 125°C; SizeZ_mm: 10.2; SizeX_mm: 11; SizeY_mm: 10.3; Value2: 63V; SizeArea_mm2: 113.3; CompType: Capacitor; Cap_F: 80uF; IRMS_A: 1.4A; AEC Category: Q200
C16 C26 = CMP-0007969-2: CAP, CERM, 0.1 uF, 100 V, +/- 10%, X7R, AEC-Q200 Grade 1, 0805; Manufacturer: TDK; TaMin_C: -55°C; ESR_ohm: 20.726m; Polarized: N; SizeAreaWB_mm2: 6.75; Value1: 0.020726 ohm; U/M: EA; Value: 0.1uF; TaMax_C: 125°C; SizeZ_mm: 1.45; SizeX_mm: 2; SizeY_mm: 1.25; SizeArea_mm2: 2.5; AEC Qualified: Y; IRMS_A: 1.456A; AEC Grade: 1; AEC Category: Q200
C17 C27 = CMP-0007082-4: CAP, CERM, 0.01 uF, 100 V, +/- 10%, X7R, AEC-Q200 Grade 1, 0603; Manufacturer: TDK; TaMin_C: -55°C; ESR_ohm: 0.2354; Polarized: N; SizeAreaWB_mm2: 4.68; Value1: 0.235428 ohm; U/M: EA; Value: 0.01uF; TaMax_C: 125°C; SizeZ_mm: 1; SizeX_mm: 1.6; SizeY_mm: 0.8; SizeArea_mm2: 1.28; AEC Qualified: Y; IRMS_A: 396.995mA; AEC Category: Q200
C18 C28 = CMP-0007081-4: CAP, CERM, 1000 pF, 100 V, +/- 10%, X7R, AEC-Q200 Grade 1, 0603; Manufacturer: TDK; TaMin_C: -55°C; ESR_ohm: 1.9714; Polarized: N; SizeAreaWB_mm2: 4.68; Value1: 1.97137 ohm; U/M: EA; Value: 1000pF; TaMax_C: 125°C; SizeZ_mm: 1; SizeX_mm: 1.6; SizeY_mm: 0.8; SizeArea_mm2: 1.28; AEC Qualified: Y; IRMS_A: 305.705mA; AEC Category: Q200
C20 = CMP-0012603-3: CAP, Polymer Hybrid, 47 uF, 80 V, +/- 20%, 36 mohm, 10x10 SMD; Manufacturer: Panasonic; TaMin_C: -55°C; ESR_ohm: 30; Polarized: Y; SizeAreaWB_mm2: 159.9; Value1: 0.036 ohm; Value: 56uF; TaMax_C: 125°C; SizeZ_mm: 10.2; SizeX_mm: 11; SizeY_mm: 10.3; Value2: 63V; SizeArea_mm2: 113.3; CompType: Capacitor; Cap_F: 80uF; IRMS_A: 1.4A; AEC Category: Q200
C30 C63 = CMP-0007077-5: CAP, CERM, 0.1 uF, 25 V, +/- 10%, X7R, AEC-Q200 Grade 1, 0603; Manufacturer: TDK; TaMin_C: -55°C; Polarized: N; SizeAreaWB_mm2: 4.68; Value1: Unknown; U/M: EA; Value: 0.1uF; TaMax_C: 125°C; SizeZ_mm: 1; SizeX_mm: 1.6; SizeY_mm: 0.8; Cap_Case: 0603; Value2: 25V; SizeArea_mm2: 1.28; AEC Qualified: Y; Cap_F: 100nF; AEC Category: Q200
C31 C64 = CMP-0009221-2: CAP, CERM, 47 uF, 10 V, +/- 20%, X7R, 1210; Manufacturer: MuRata; TaMin_C: -55°C; Polarized: N; SizeAreaWB_mm2: 14.7; Value1: Unknown; U/M: EA; Value: 47uF; TaMax_C: 125°C; SizeZ_mm: 2.7; SizeX_mm: 3.2; SizeY_mm: 2.5; SizeArea_mm2: 8; Cap_F: 47µF; AEC Category: Q200
C32-C62 C65-C91 = CMP-0009221-2: CAP, CERM, 47 uF, 10 V, +/- 20%, X7R, 1210; Manufacturer: MuRata; TaMin_C: -55°C; Polarized: N; SizeAreaWB_mm2: 14.7; Value1: Unknown; U/M: EA; Value: 47uF; TaMax_C: 125°C; SizeZ_mm: 2.7; SizeX_mm: 3.2; SizeY_mm: 2.5; Value2: 10V; SizeArea_mm2: 8; Cap_F: 47µF; AEC Category: Q200
Ccomp1 Ccomp2 = CMP-0007089-5: CAP, CERM, 6800 pF, 100 V, +/- 10%, X7R, AEC-Q200 Grade 1, 0603; Manufacturer: TDK; TaMin_C: -55°C; ESR_ohm: 0.352; Polarized: N; SizeAreaWB_mm2: 4.68; Value1: 0.35202 ohm; U/M: EA; Value: 6800pF; TaMax_C: 125°C; SizeZ_mm: 1; SizeX_mm: 1.6; SizeY_mm: 0.8; Value2: 100V; SizeArea_mm2: 1.28; AEC Qualified: Y; IRMS_A: 345.58mA; AEC Category: Q200
Ccs1 Ccs2 = CMP-0006897-4: CAP, CERM, 2200 pF, 50 V, +/- 10%, X7R, 0603; Manufacturer: Kemet; TaMin_C: -55°C; Polarized: N; SizeAreaWB_mm2: 4.68; Value1: Unknown; U/M: EA; Value: 2200pF; TaMax_C: 125°C; SizeZ_mm: 1; SizeX_mm: 1.6; SizeY_mm: 0.8; SizeArea_mm2: 1.28; AEC Category: Q200
Cdith = CMP-0007468-5: CAP, CERM, 0.01 uF, 100 V, +/- 10%, X7R, 0603; Manufacturer: MuRata; TaMin_C: -55°C; Polarized: N; SizeAreaWB_mm2: 4.68; Value1: Unknown; U/M: EA; Value: 0.01uF; TaMax_C: 125°C; SizeZ_mm: 1; SizeX_mm: 1.6; SizeY_mm: 0.8; Value2: 100V; SizeArea_mm2: 1.28; CompType: Capacitor; Cap_F: 10nF; AEC Category: Q200
Chf1 Chf2 = CMP-0080062-1: CAP, CERM, 47 pF, 50 V,+/- 5%, C0G/NP0, AEC-Q200 Grade 0, 0603; Manufacturer: TDK; PartNumber: CGA3E2NP01H470J080AA; TaMin_C: -55°C; Polarized: N; SizeAreaWB_mm2: 4.68; U/M: EA; Value: 47pF; TaMax_C: 150°C; SizeZ_mm: 1; SizeX_mm: 1.6; SizeY_mm: 0.8; Value2: 50V; SizeArea_mm2: 1.28; AEC Qualified: Y; AEC Grade: 0; AEC Category: Q200
Cpi1 Cpi2 = CMP-0085951-1: CAP, CERM, 10 µF, 75 V,+/- 20%, X7R, AEC-Q200 Grade 1, 1210; Manufacturer: TDK; Value2: 75V; SizeX_mm: 3.2; Cap_Case: 1210; AEC Qualified: Y; Polarized: N; AEC Category: Q200; U/M: EA; SizeZ_mm: 2.8; SizeY_mm: 2.5; TaMin_C: -55°C; AEC Grade: 1; SizeAreaWB_mm2: 14.7; SizeArea_mm2: 8; TaMax_C: 125°C; Value: 10uF
Cpi7 = CMP-0007969-2: CAP, CERM, 0.1 uF, 100 V, +/- 10%, X7R, AEC-Q200 Grade 1, 0805; Manufacturer: TDK; TaMin_C: -55°C; ESR_ohm: 20.726m; Polarized: N; SizeAreaWB_mm2: 6.75; Value1: 0.020726 ohm; U/M: EA; Value: 0.1uF; TaMax_C: 125°C; SizeZ_mm: 1.45; SizeX_mm: 2; SizeY_mm: 1.25; Value2: 100V; SizeArea_mm2: 2.5; AEC Qualified: Y; IRMS_A: 1.456A; AEC Grade: 1; AEC Category: Q200
Cpi8 = CMP-0007082-4: CAP, CERM, 0.01 uF, 100 V, +/- 10%, X7R, AEC-Q200 Grade 1, 0603; Manufacturer: TDK; TaMin_C: -55°C; ESR_ohm: 0.2354; Polarized: N; SizeAreaWB_mm2: 4.68; Value1: 0.235428 ohm; U/M: EA; Value: 0.01uF; TaMax_C: 125°C; SizeZ_mm: 1; SizeX_mm: 1.6; SizeY_mm: 0.8; Value2: 100V; SizeArea_mm2: 1.28; AEC Qualified: Y; IRMS_A: 396.995mA; AEC Category: Q200
Cpi9 = CMP-0007081-4: CAP, CERM, 1000 pF, 100 V, +/- 10%, X7R, AEC-Q200 Grade 1, 0603; Manufacturer: TDK; TaMin_C: -55°C; ESR_ohm: 1.9714; Polarized: N; SizeAreaWB_mm2: 4.68; Value1: 1.97137 ohm; U/M: EA; Value: 1000pF; TaMax_C: 125°C; SizeZ_mm: 1; SizeX_mm: 1.6; SizeY_mm: 0.8; Value2: 100V; SizeArea_mm2: 1.28; AEC Qualified: Y; IRMS_A: 305.705mA; AEC Category: Q200
Cres Css1 Css2 = CMP-0080102-1: CAP, CERM, 0.22 µF, 16 V,+/- 10%, X7R, AEC-Q200 Grade 1, 0603; Manufacturer: Samsung; TaMin_C: -55°C; Polarized: N; SizeAreaWB_mm2: 4.68; U/M: EA; Value: 0.22uF; TaMax_C: 125°C; SizeZ_mm: 1; SizeX_mm: 1.6; SizeY_mm: 0.8; Value2: 16V; SizeArea_mm2: 1.28; CompType: Capacitor; AEC Qualified: Y; Cap_F: 220nF; AEC Category: Q200
D1 D3 = CMP-0080760-2: Diode, Schottky, 100 V, 0.15 A, AEC-Q101, SOD-123; Manufacturer: Vishay-Semiconductor; SizeArea_mm2: 6.545; Io_A: 150mA; Vr_V: 100V; Value: 100V; SizeAreaWB_mm2: 13.095; AEC Qualified: Y; Vf_V: 1V; SizeZ_mm: 1.35; Value1: 0.15A; TJmax_C: 125°C; SizeY_mm: 1.7; SizeX_mm: 3.85; AEC Category: Q101
D2 D4 D5 = CMP-0098370-1: Diode Schottky 100V 250mA Surface Mount DFN1006BD-2; Manufacturer: Nexperia; AEC Qualified: Yes; SizeZ_mm: 0.5mm; TJmax_C: 150°C; AEC Grade: Grade 0; Cap_F: 25pF; Max Surge Forward Current: 2.5A; Peak Reverse Current: 9uA; TaMax_C: +150°C; TaMin_C: -55°C
J1 = CMP-0055161-1: TEST POINT SLOTTED .118", TH; Manufacturer: Keystone; CNHeader: FALSE; Green_Lifecycle: Active; Green_REACh: Passed; CT: TRUE
J2 = CMP-0054586-1: Header, 2.54 mm, 12x1, Gold, TH; Manufacturer: Sullins Connector Solutions; CT: FALSE; CNHeader: TRUE; Cert_UL: Y; Current_A: 3A; Gender: Male; Pitch_mm: 2.54; Row_Count: 1; Shrouded: N; Voltage_V: 1.8kV
J11 = CMP-0074910-1: Terminal Block, 5.08 mm, 2x1, Brass, TH; Manufacturer: On-Shore Technology; Cert_VDE: Y; CNHeader: False; Current_A: 15A; Green_Lifecycle: Not Set; Shrouded: N; Gender: Female; Green_REACh: Incomplete; Voltage_V: 300V; Row_Count: 1; Pitch_mm: 5.08; CT: True
J33 J50 = CMP-0074939-1: Terminal Block, 5.08 mm, 4x1, Brass, TH; Manufacturer: On-Shore Technology; Cert_VDE: Y; CNHeader: False; Current_A: 15A; Green_Lifecycle: Not Set; Shrouded: N; Gender: Female; Green_REACh: Incomplete; Voltage_V: 300V; Row_Count: 1; Pitch_mm: 5.08; CT: True
J100 J200 = CMP-0054947-1: Header, 100mil, 2x1, Gold, TH; Manufacturer: TE Connectivity; Green_Lifecycle: Active; Green_REACh: Passed; CNHeader: TRUE; CT: FALSE
J101 = CMP-0075554-1: Connector, MMCX 50 ohm, TH; Manufacturer: Samtec; CT: False; Gender: Female
J102 J201 J202 = CMP-0075554-1: Connector, MMCX 50 ohm, TH; CT: False; Gender: Female
L1 = CMP-0090553-1: XAL1350 Series Shielded Power Inductors 23A as RMS Current, 1 MHz Test Frequency, 30% Tolerance, 1.3uH and AEC Qualified Grade 1; SizeZ_mm: 5mm; Tolerance_%: 20%; AEC Qualified: Yes; DCR_ohm: 2.7m; Test Frequency: 1MHz; Ind_H: 1.3µH; Material: Composite; Irms: 32A; Shrouded: true; Self Resonant Frequency: 33MHz; TaMax_C: +125°C; TaMin_C: -40°C; Isat: 56A; AEC Grade: Grade 1
L2 = CMP-0060967-1: Inductor, Shielded, Composite, 2.2 uH, 24 A, 0.0042 ohm, SMD; Isat: 46A @ 30% inductance drop; Irms: 24A @ 40C rise; DCR_ohm: 4.2m; Value: 2.2uH; Imax_A: 24A; SizeZ_mm: 5; SizeAreaWB_mm2: 240; SizeX_mm: 13; SizeY_mm: 14; SizeArea_mm2: 182; Ind_H: 2.2µH; AEC Qualified: N; AEC Category: Q200
Lcm = CMP-0013118-2: Coupled inductor, 8 A, 0.006 ohm, SMD; Manufacturer: TDK; DCR_ohm: 6m
Lpi = CMP-0120492-1: 10 µH Shielded Molded Inductor 12.1 A 18mOhm Max Nonstandard; Manufacturer: Coilcraft; AEC Grade: Grade 1; AEC Qualified: Yes; DCR_ohm: 18m; Ind_H: 10µH; Irms: 12.1A; Isat: 6.5A; SizeZ_mm: 6mm; Value: 10uH; Self Resonant Frequency: 12MHz; Shrouded: true; TaMax_C: +125°C; TaMin_C: -40°C; Test Frequency: 1MHz; Tolerance_%: 20%
Lpi-hf = CMP-0003396-1: Ferrite Bead, 800 ohm @ 100 MHz, 8 A, 2220; Manufacturer: Laird-Signal Integrity Products; Ztyp@1GHz_Ohm: 75; ZTyp@100MHz_Ohm: 800; SizeAreaWB_mm2: 53.96; DCR_ohm: 10m; Value1: 0.01 ohm; Value: 800 ohm; Imax_A: 8A; SizeZ_mm: 3.9; SizeX_mm: 5.6; SizeY_mm: 5.1; SizeArea_mm2: 28.56
NT1 NTv1 NTv2 = CMP-0078142-6: Single point connection between nets.
Q1 Q3 = CMP-0092446-1: N-Channel 11A (Ta), 42A (Tc) 3.6W (Ta), 54W (Tc) Surface Mount 5-DFN (5x6) (8-SOFL); Manufacturer: ON Semiconductor; Rthja Max: 42°C/W; Drain To Source Breakdown Voltage: 80V; AEC Grade: Grade 0; Transconductance: 55S; Turn On Delay Time: 29ns; VdsMax_V: 1.2V; Typ Forward Diode Voltage: 0.81V; QgTyp_nC: 17nC @ 10V; Reverse Recovery Charge: 25nC; Turn Off Delay Time: 18ns; TJmax_C: +175°C; AEC Qualified: Yes; Reverse Recovery Time: 32ns; Input Capacitace At Vds: 906pF @ 40V; Standoff Height: 0mm; Threshold Vgs Max: 2V; Rdson45_ohm: 13.4m; Vgs_V: 20V; SizeZ_mm: 1.1mm; Number Of Channels: 1; ChMode: False; Pulse Drain Current: 208A
Q2 Q4 = CMP-0120368-2: MOSFET N-Channel 80 V 20A (Ta), 110A (Tc) 3.8W (Ta), 116W (Tc) Surface Mount, Wettable Flank 5-DFN (5x6) (8-SOFL); Manufacturer: onsemi; AEC Qualified: Yes; QgTyp_nC: 52nC @ 10V; Rdson45_ohm: 4.1m; SizeZ_mm: 1.1mm; VdsMax_V: 1.2V; Vgs_V: 20V; ChMode: False; AEC Grade: Grade 0; Drain To Source Breakdown Voltage: 80V; Input Capacitace At Vds: 2900pF @ 40V; Number Of Channels: 1; Pulse Drain Current: 722A; Reverse Recovery Charge: 59nC; Reverse Recovery Time: 52ns; Rthja Max: 40°C/W; Standoff Height: 0mm; Threshold Vgs Max: 2V; TJmax_C: +175°C; Transconductance: 178S; Turn Off Delay Time: 35ns; Turn On Delay Time: 19ns; Typ Forward Diode Voltage: 0.79V
Q100 Q200 = CMP-0000593-2: MOSFET, N-CH, 30 V, 20 A, DNH0008A (VSONP-8); Manufacturer: Texas Instruments; Alternate Manufacturer: None; ChType: N; Value: 30V; Value1: 0.014; Rdson45_ohm: 14.2m; Value2: 5.3 nC; QgTyp_nC: 5.3; Vgs_V: 20V; IdsMax_A: 20A; SizeAreaWB_mm2: 18.49; SizeArea_mm2: 10.89; SizeX_mm: 3.3; SizeZ_mm: 0.9; AEC Category: Q101; ChMode: Enhancement
R1 R2 = CMP-0120372-1: Res Metal Strip 1020 0.002 Ohm 1% 2W ±50ppm/C Sulfur Resistant Wide Terminal SMD Automotive T/R; Manufacturer: Vishay; AEC Grade: Grade 0; AEC Qualified: Yes; SizeZ_mm: 0.762mm; TempCo: 50ppm/°C
R3 = CMP-0022900-4: RES, 1.00, 1%, 0.1 W, 0603; Manufacturer: Yageo; Power_W: 100mW; TempCo: 200 ppm/C; Value_Code: 1R00; Value: 1.00; EIA_Code: E96; Res_ohm: 1; SizeX_mm: 1.6; SizeY_mm: 0.8; Value2: 0.1W; SizeArea_mm2: 1.28; CompType: Resistor; AEC Qualified: N; VDC_V: 75V; AEC Category: Q200; SizeAreaWB_mm2: 4.68
R4 R5 = CMP-0025834-4: RES, 5.1, 5%, 0.1 W, AEC-Q200 Grade 0, 0603; Manufacturer: Vishay-Dale; Power_W: 100mW; TempCo: 200 ppm/C; Value_Code: 5R10; Value: 5.1; EIA_Code: E24; SizeX_mm: 1.6; SizeY_mm: 0.8; SizeZ_mm: 1; Value2: 0.1W; SizeArea_mm2: 1.28; AEC Qualified: Y; VDC_V: 75V; AEC Category: Q200; AEC Grade: 0
R6 R11-R13 Rdivt1 Rdivt2 = CMP-0021990-4: RES, 100 k, 1%, 0.1 W, AEC-Q200 Grade 0, 0603; Manufacturer: Vishay-Dale; Power_W: 100mW; TempCo: 100 ppm/C; Value: 100k; EIA_Code: E96; SizeX_mm: 1.6; SizeY_mm: 0.8; SizeZ_mm: 1; Value2: 0.1W; SizeArea_mm2: 1.28; CompType: Resistor; AEC Qualified: Y; VDC_V: 75V; AEC Category: Q200; AEC Grade: 0
R7 R8 = CMP-0097597-1: RES Thick Film, 2.2Ω, 5%, 0.1W, 200ppm/°C, 0603; Manufacturer: Vishay; Approved Alternate Part Number: 541-1.00HHCT-ND; VDC_V: 75V; AEC Qualified: Yes; AEC Grade: Grade 0; Power: 100mW; SizeZ_mm: 0.5mm
R9 R10 Rmode = CMP-0025697-4: RES, 0, 5%, 0.1 W, AEC-Q200 Grade 0, 0603; Manufacturer: Vishay-Dale; Power_W: 100mW; TempCo: 200 ppm/C; Value_Code: 0000; Value: 0; EIA_Code: E24; SizeX_mm: 1.6; SizeY_mm: 0.8; SizeZ_mm: 1; Value2: 0.1W; SizeArea_mm2: 1.28; CompType: Resistor; AEC Qualified: Y; VDC_V: 75V; AEC Category: Q200
R100 R200 = CMP-0087671-1: 100 mOhms ±1% 2W Chip Resistor Wide 1020, 1020 Automotive AEC-Q200, Current Sense, Moisture Resistant Thick Film; PartNumber: RCWE1020R115FKEA; Manufacturer: Vishay; TempCo: 100ppm/°C; AEC Qualified: Yes; Symbol Name: SYM-RCWE1020R115FKEA; AEC Grade: Grade 0; SizeZ_mm: 0.7mm
R101 R102 R201 R202 = CMP-0022448-4: RES, 49.9, 1%, 0.1 W, AEC-Q200 Grade 0, 0603; Manufacturer: Vishay-Dale; Power_W: 100mW; TempCo: 100 ppm/C; Value_Code: 49R9; Value: 49.9; EIA_Code: E96; SizeX_mm: 1.6; SizeY_mm: 0.8; SizeZ_mm: 1; Value2: 0.1W; SizeArea_mm2: 1.28; AEC Qualified: Y; VDC_V: 75V; AEC Category: Q200; AEC Grade: 0
R103 R203 = CMP-0025743-4: RES, 1.0, 5%, 0.1 W, AEC-Q200 Grade 0, 0603; Manufacturer: Vishay-Dale; Power_W: 100mW; TempCo: 200 ppm/C; Value_Code: 1R00; Value: 1.0; EIA_Code: E24; Res_ohm: 1; SizeX_mm: 1.6; SizeY_mm: 0.8; Value2: 0.1W; SizeArea_mm2: 1.28; AEC Qualified: Y; VDC_V: 75V; AEC Category: Q200; AEC Grade: 0
R104 R204 Rpg1 Rpg2 = CMP-0021998-4: RES, 10.0 k, 1%, 0.1 W, AEC-Q200 Grade 0, 0603; Manufacturer: Vishay-Dale; Power_W: 100mW; TempCo: 100 ppm/C; Value_Code: 10k0; Value: 10.0k; EIA_Code: E96; Res_ohm: 10k; SizeX_mm: 1.6; SizeY_mm: 0.8; SizeZ_mm: 1; Value2: 0.1W; SizeArea_mm2: 1.28; AEC Qualified: Y; VDC_V: 75V; AEC Category: Q200; AEC Grade: 0
Rbode1 Rbode2 = CMP-0025704-4: RES, 10, 5%, 0.25 W, AEC-Q200 Grade 0, 0603; Manufacturer: Vishay-Dale; Power_W: 250mW; TempCo: 200 ppm/C; Value_Code: 10R0; Value: 10; EIA_Code: E24; SizeX_mm: 1.6; SizeY_mm: 0.8; SizeZ_mm: 1; Value2: 0.25W; SizeArea_mm2: 1.28; AEC Qualified: Y; VDC_V: 75V; AEC Category: Q200; AEC Grade: 0
Rcomp1 = CMP-0022042-4: RES, 13.0 k, 1%, 0.1 W, AEC-Q200 Grade 0, 0603; Manufacturer: Vishay-Dale; Power_W: 100mW; TempCo: 100 ppm/C; Value_Code: 13k0; Value: 13.0k; EIA_Code: E96; Res_ohm: 13k; SizeX_mm: 1.6; SizeY_mm: 0.8; SizeZ_mm: 1; Value2: 0.1W; SizeArea_mm2: 1.28; AEC Qualified: Y; VDC_V: 75V; AEC Category: Q200; AEC Grade: 0
Rcomp2 = CMP-0022017-4: RES, 11.3 k, 1%, 0.1 W, AEC-Q200 Grade 0, 0603; Manufacturer: Vishay-Dale; Power_W: 100mW; TempCo: 100 ppm/C; Value_Code: 11k3; Value: 11.3k; EIA_Code: E96; SizeX_mm: 1.6; SizeY_mm: 0.8; SizeZ_mm: 1; Value2: 0.1W; SizeArea_mm2: 1.28; AEC Qualified: Y; VDC_V: 75V; AEC Category: Q200; AEC Grade: 0
Rcs1 Rcs2 = CMP-0021991-4: RES, 100, 1%, 0.1 W, AEC-Q200 Grade 0, 0603; Manufacturer: Vishay-Dale; Power_W: 100mW; TempCo: 100 ppm/C; Value_Code: 100R; Value: 100; EIA_Code: E96; SizeX_mm: 1.6; SizeY_mm: 0.8; SizeZ_mm: 1; Value2: 0.1W; SizeArea_mm2: 1.28; AEC Qualified: Y; VDC_V: 75V; AEC Category: Q200; AEC Grade: 0
Rd1 Rd2 = CMP-0093440-1: 1 Ohms ±1% 1W Chip Resistor 2512 (6432 Metric) Automotive AEC-Q200, Current Sense Thick Film; Manufacturer: KOA Speer; Value: 1; AEC Qualified: Yes; SizeZ_mm: 0.7mm; TempCo: 100ppm/°C; AEC Grade: Grade 0
Rdiv5-b Rdiv5-t = CMP-0022200-4: RES, 200 k, 1%, 0.1 W, AEC-Q200 Grade 0, 0603; Manufacturer: Vishay-Dale; Power_W: 100mW; TempCo: 100 ppm/C; Value: 200k; EIA_Code: E96; SizeX_mm: 1.6; SizeY_mm: 0.8; SizeZ_mm: 1; Value2: 0.1W; SizeArea_mm2: 1.28; AEC Qualified: Y; VDC_V: 75V; AEC Category: Q200; AEC Grade: 0
Rdivb1 = CMP-0022220-4: RES, 22.1 k, 1%, 0.1 W, AEC-Q200 Grade 0, 0603; Manufacturer: Vishay-Dale; Power_W: 100mW; TempCo: 100 ppm/C; Value_Code: 22k1; Value: 22.1k; EIA_Code: E96; SizeX_mm: 1.6; SizeY_mm: 0.8; SizeZ_mm: 1; Value2: 0.1W; SizeArea_mm2: 1.28; CompType: Resistor; AEC Qualified: Y; VDC_V: 75V; AEC Category: Q200; AEC Grade: 0
Rdivb2 = CMP-0022044-4: RES, 13.7 k, 1%, 0.1 W, AEC-Q200 Grade 0, 0603; Manufacturer: Vishay-Dale; Power_W: 100mW; TempCo: 100 ppm/C; Value_Code: 13k7; Value: 13.7k; EIA_Code: E96; SizeX_mm: 1.6; SizeY_mm: 0.8; SizeZ_mm: 1; Value2: 0.1W; SizeArea_mm2: 1.28; CompType: Resistor; AEC Qualified: Y; VDC_V: 75V; AEC Category: Q200; AEC Grade: 0
Ren1 Ren2 = CMP-0022492-4: RES, 549 k, 1%, 0.1 W, AEC-Q200 Grade 0, 0603; Manufacturer: Vishay-Dale; Power_W: 100mW; TempCo: 100 ppm/C; Value: 549k; EIA_Code: E96; SizeX_mm: 1.6; SizeY_mm: 0.8; SizeZ_mm: 1; Value2: 0.1W; SizeArea_mm2: 1.28; AEC Qualified: Y; VDC_V: 75V; AEC Category: Q200; AEC Grade: 0
Rfb3-1 = CMP-0025697-4: RES, 0, 5%, 0.1 W, AEC-Q200 Grade 0, 0603; Manufacturer: Vishay-Dale; Power_W: 100mW; TempCo: 200 ppm/C; Value_Code: 0000; Value: 0; EIA_Code: E24; SizeX_mm: 1.6; SizeY_mm: 0.8; SizeZ_mm: 1; Value2: 0.1W; SizeArea_mm2: 1.28; AEC Qualified: Y; VDC_V: 75V; AEC Category: Q200
Rt = CMP-0022663-4: RES, 97.6 k, 1%, 0.1 W, AEC-Q200 Grade 0, 0603; Manufacturer: Vishay-Dale; Power_W: 100mW; TempCo: 100 ppm/C; Value_Code: 97k6; Value: 97.6k; EIA_Code: E96; SizeX_mm: 1.6; SizeY_mm: 0.8; SizeZ_mm: 1; Value2: 0.1W; SizeArea_mm2: 1.28; AEC Qualified: Y; VDC_V: 75V; AEC Category: Q200; AEC Grade: 0
TP1 TP2 TP4 TP5 TP8 TP9 = CMP-0055121-1: Terminal, Turret, TH, Triple; Manufacturer: Keystone; CT: FALSE; Green_REACh: Passed; CompType: Turret Terminal; Green_Lifecycle: Active
TP3 TP6 = CMP-0055152-2: Test Point, Miniature, SMT; Manufacturer: Keystone Electronics; CNHeader: FALSE; Green_Lifecycle: Active; Green_REACh: Passed; CT: TRUE
TP11 TP14 = CMP-0055147-2: Test Point, Multipurpose, Red, TH; Manufacturer: Keystone Electronics; CT: TRUE; ContactFinish: Silver; Green_Lifecycle: Active; CNHeader: FALSE; Green_REACh: Passed
TP12 TP15 = CMP-0055149-2: Test Point, Multipurpose, White, TH; Manufacturer: Keystone Electronics; ContactFinish: Silver; CT: TRUE; CNHeader: FALSE; Green_Lifecycle: Active; Green_REACh: Passed
TP13 TP16 = CMP-0055148-2: Test Point, Multipurpose, Black, TH; Manufacturer: Keystone Electronics; CNHeader: FALSE; ContactFinish: Silver; Green_REACh: Passed; Green_Lifecycle: Active; CT: TRUE
TPsns5V = CMP-0055140-2: Test Point, Miniature, Orange, TH; Manufacturer: Keystone Electronics; Green_Lifecycle: Active; ContactFinish: Silver; CNHeader: FALSE; CT: TRUE; Green_REACh: Passed
U1 = CMP-0094639-1: Automotive 3.5-V to 65-V Dual Synchronous Buck Controller With Low IQ; Manufacturer: Texas Instruments; TaMin_C: -40°C; SizeZ_mm: 1mm; Switching Frequency: 0.1-2.2MHz; Standoff Height: 0mm; Number Of Outputs: 2; AEC Grade: Grade 1; Output Type: Fixed,AdjustableProgrammable; TJmax_C: +150°C; Min Supply Voltage: 3.5V; AEC Qualified: Yes; Nominal Supply Current: 15-25uA; TaMax_C: +125°C; Output Voltage: 0.6-55V; Max Supply Voltage: 65V

## Sheet PMP23452_Hardware&misc.SchDoc: PMP23452 Hardware
size 431 x 279 mm; Date: Not shown in title block; ApprovedBy: Not shown in title block; CheckedBy: Not shown in title block; Author: Not shown in title block; CompanyName: Not shown in title block; Engineer: Not shown in title block; Organization: Not shown in title block; Address1: Not shown in title block; Address2: Not shown in title block; Address3: Not shown in title block; Address4: Not shown in title block; DocumentNumber: 2; Revision: Use project parameter SCH_Rev; SheetNumber: 2; SheetTotal: 2; PageSetup: Record=PageOptions¦CenterHorizontal=True¦CenterVertical=True¦PrintScale=1.00¦XCorrection=1.00¦YCorrection=1.00¦PrintKind=0¦BorderSize=5000000¦LeftOffset=0¦BottomOffset=0¦Orientation=2¦PaperLength=1000¦PaperWidth=1000¦Scale=100¦PaperSource=15¦PrintQuality=600¦MediaType=1¦DitherType=10¦PaperKind=Letter¦PrintScaleMode=1
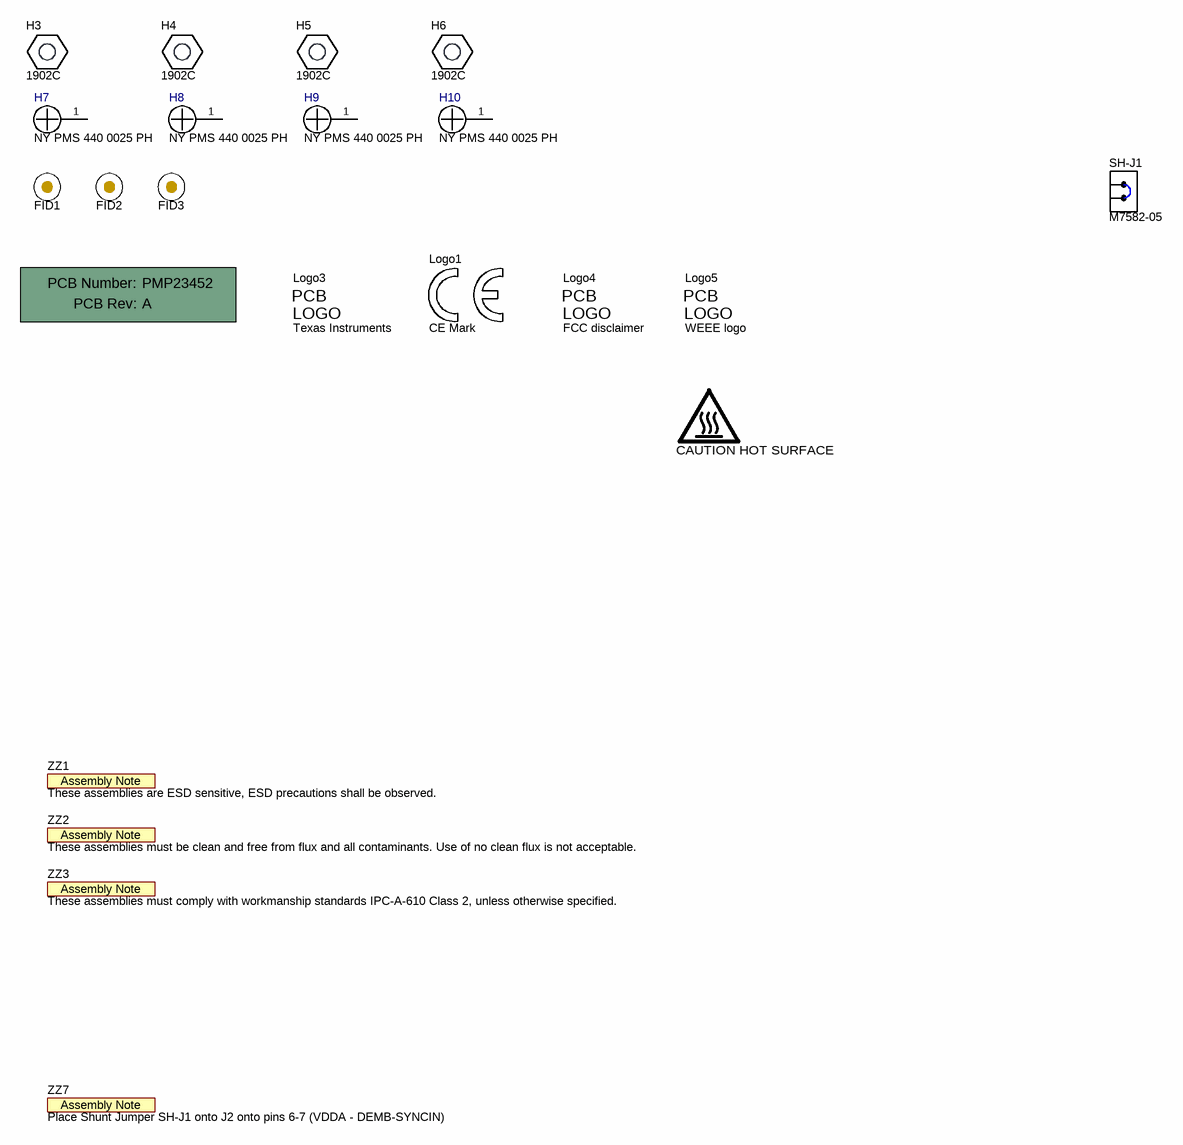
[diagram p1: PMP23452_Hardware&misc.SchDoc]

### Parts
!PCB1  Printed Circuit Board  (value not drawn)  (mechanical)
FID1  Fiducial  [Fiducial10-20]  (value not drawn)
FID2  Fiducial  [Fiducial10-20]  (value not drawn)
FID3  Fiducial  [Fiducial10-20]  (value not drawn)
H3  1902C  [Keystone_1902C]
H4  1902C  [Keystone_1902C]
H5  1902C  [Keystone_1902C]
H6  1902C  [Keystone_1902C]
H7  NY PMS 440 0025 PH  [NY PMS 440 0025 PH]
H8  NY PMS 440 0025 PH  [NY PMS 440 0025 PH]
H9  NY PMS 440 0025 PH  [NY PMS 440 0025 PH]
H10  NY PMS 440 0025 PH  [NY PMS 440 0025 PH]
Logo1  CE Mark  [CE_Mark_5mm]  (no BOM)
LOGO2  CAUTION HOT SURFACE  [IEC_HotSurface_Small]  (no BOM)
Logo3  Texas Instruments  [TI_Stacked_Overlay_Small]  (no BOM)
Logo4  FCC disclaimer  [FCC_disclaimer]  (no BOM)
Logo5  WEEE logo  [WEEE_Minimum]  (no BOM)
SH-J1  M7582-05  [Harwin_M7582-05]  (mechanical)
ZZ1  These assemblies are ESD sensitive, ESD precautions shall be observed.  [AssemblyNote]  (no BOM)
ZZ2  These assemblies must be clean and free from flux and all contaminants. Use of no clean flux is not acceptable.  [AssemblyNote]  (no BOM)
ZZ3  These assemblies must comply with workmanship standards IPC-A-610 Class 2, unless otherwise specified.  [AssemblyNote]  (no BOM)
ZZ7  Place Shunt Jumper SH-J1 onto J2 onto pins 6-7 (VDDA - DEMB-SYNCIN)  [AssemblyNote]  (no BOM)

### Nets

Not connected (* = marked no-connect by the designer): H7 1; H8 1; H9 1; H10 1

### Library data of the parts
!PCB1 = CMP-0003618-2: Manufacturer: Any; PartNumber: PMP23452
FID1-FID3 = CMP-0077181-1: Fiducial mark.  There is nothing to buy or mount.
H3-H6 = CMP-0003610-1: Standoff, Hex, 0.5"L #4-40 Nylon; Manufacturer: Keystone; CompType: Hardware
H7-H10 = CMP-0003617-1: Machine Screw, Round, #4-40 x 1/4, Nylon, Philips panhead; Manufacturer: B&F Fastener Supply; CompType: Hardware
Logo1 = CMP-0074844-1: SymbolCreator: a0412235
LOGO2 = CMP-0074837-2: IEC 61010-1 Hot Surface Warning; Manufacturer: Texas Instruments; SymbolCreator: a0412235; CompType: IC; AEC Category: Q200
Logo3 = CMP-0074838-1: Texas Instrument Corporate Signature; SymbolCreator: a0412235; Lib Reference: TI_Logo; Library Reference: Logo
Logo4 = CMP-0074847-1: FCC_disclaimer; Library Reference: Logo
Logo5 = CMP-0074769-3: Manufacturer: Texas Instruments; AEC Category: Q200; CompType: IC
SH-J1 = CMP-0078738-1: Single Operation 2.54mm Pitch Open Top Jumper Socket; Manufacturer: Harwin; CompType: Shunt
ZZ1 = CMP-0077236-1
ZZ2 = CMP-0077237-1
ZZ3 = CMP-0077238-1
ZZ7 = CMP-0077238-1: Place Shunt Jumper SH-J1 onto J2 pins VDDA - DEMB

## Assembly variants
001: not fitted FID1 FID2 FID3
